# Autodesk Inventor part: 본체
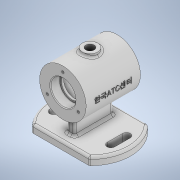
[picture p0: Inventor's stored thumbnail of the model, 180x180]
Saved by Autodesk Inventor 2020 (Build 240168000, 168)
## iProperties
Created: 2021-09
Part Number: 본체
Material: Generic
Document SubType Name: Modeling
Designer: Administrator
Density: 1 g/cm^3
Appearance: Default
Author: Administrator
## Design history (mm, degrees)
sketch "스케치1"
  geometry: C1 r 30 at (0, 0); 1 further point
  constraints: 1 centre point, 1 coincident
  dimensions: "d0" = 60 diameter of C1
extrude "돌출1" new body sketch "스케치1" stored distance "d1" = 70; taper "d2" = 0 deg
node "작업 평면1"
sketch "스케치2"
  geometry: C1 r 52.5 at (0, 0); 1 further point
  constraints: 1 centre point, 1 coincident
  dimensions: "d4" = 105 diameter of C1
extrude "돌출2" join sketch "스케치2" distance "d5" = 10; taper "d6" = 0 deg
sketch "스케치3"
  geometry: L1 (36.458, 37.5)-(-36.458, 37.5); L2 (-36.458, -37.5)-(36.458, -37.5); L3 (-36.458, -37.5)-(-36.742, -37.5); L4 (36.458, -37.5)-(36.742, -37.5); L5 (36.458, 37.5)-(36.742, 37.5); L6 (-36.458, 37.5)-(-36.742, 37.5); A1 r 52.5 centre (0, 0) between (-36.742, -37.5) and (36.742, -37.5) reference; A2 r 52.5 centre (0, 0) between (-36.742, -37.5) and (36.742, -37.5) reference; 3 further points
  constraints: 12 end point, 4 horizontal, 4 point on circle, 1 parallel, 1 point on line
  dimensions: "d7" = 75 distance of L1.end L2.start
extrude "돌출3" cut sketch "스케치3" distance "d8" = 10; taper "d9" = 0 deg
sketch "스케치4"
  geometry: L1 (-25.13, 25)-(-60.104, 25); L2 (-60.104, 25)-(-60.104, -25); L3 (-60.104, -25)-(-25.13, -25); L4 (-25.13, -25)-(-25.13, 25); 2 further points
  constraints: 8 end point, 2 parallel, 1 horizontal, 1 horizontal alignment, 1 midpoint, 1 perpendicular
  dimensions: "d10" = 50 distance of L1.end L2.end
extrude "돌출4" join sketch "스케치4" stored distance "d11" = 10; taper "d12" = 0 deg
sketch "스케치5"
  geometry: L1 (-37, -10)-(-37, 10); L2 (-32, -10)-(-32, 10); L3 (-42, 10)-(-42, -10); L4 (0, 0)-(0, 55.124); L5 (37, -10)-(37, 10); L6 (32, -10)-(32, 10); L7 (42, 10)-(42, -10); A1 r 5 centre (-37, -10) between (-42, -10) and (-32, -10); A2 r 5 centre (-37, 10) between (-32, 10) and (-42, 10); A3 r 5 centre (37, -10) between (32, -10) and (42, -10); A4 r 5 centre (37, 10) between (42, 10) and (32, 10); 2 further points
  constraints: 18 end point, 8 point on circle, 7 symmetric about line, 4 centre point, 4 tangent, 2 vertical, 1 horizontal alignment, 1 midpoint, 1 parallel, 2 other
  dimensions: "d13" = 20 distance of L1.start L1.end; "d14" = 10 diameter of A2; "d15" = 37 distance of point (-37, 0) L4.start
extrude "돌출5" cut sketch "스케치5" distance "d16" = 10; taper "d17" = 0 deg
sketch "스케치6"
  geometry: L1 (30, 35)-(-30, 35) reference; L2 (0, 35)-(16, 35); L3 (16, 35)-(16, 23.3); L4 (15.7, 23)-(0, 23); L5 (0, 23)-(0, 35); L6 (0, 23)-(14, 23); L7 (14, 23)-(14, 20); L8 (14, 20)-(0, 20); L9 (0, 20)-(0, 23); L10 (0, 20)-(25, 20); L11 (25, 20)-(25, -20); L12 (25, -20)-(0, -20); L13 (0, -20)-(0, 20); L14 (0, -20)-(14, -20); L15 (14, -20)-(14, -23); L16 (14, -23)-(0, -23); L17 (0, -23)-(0, -20); L18 (-30, -35)-(30, -35) reference; L19 (0, -23)-(15.7, -23); L20 (16, -23.3)-(16, -35); L21 (16, -35)-(0, -35); L22 (0, -35)-(0, -23); A1 r 0.3 centre (15.7, 23.3) between (15.7, 23) and (16, 23.3); A2 r 0.3 centre (15.7, -23.3) between (16, -23.3) and (15.7, -23); 11 further points
  constraints: 40 end point, 10 parallel, 5 horizontal, 5 perpendicular, 5 point on line, 4 point on circle, 4 tangent, 3 midpoint, 2 centre point, 1 equal radius, 1 horizontal alignment
  dimensions: "d18" = 50 diameter of L11 L13; "d19" = 40 distance of L10.end L11.end; "d20" = 32 diameter of L3 L5; "d21" = 28 diameter of L7 L9; "d22" = 32 diameter of L20 L22; "d23" = 28 diameter of L15 L17; "d24" = 12 distance of point (16, -23) L20.end; "d25" = 12 distance of L2.end point (16, 23); "d26" = 0.3 radius of A1
revolve "회전1" sketch "스케치6" stored, may be unused: angle "d27" = 90 deg
node "작업 평면2"
sketch "스케치7"
  geometry: C1 r 10 at (0, 0); 1 further point
  constraints: 1 centre point, 1 coincident
  dimensions: "d29" = 20 diameter of C1
extrude "돌출6" join sketch "스케치7" stored distance "d30" = 10; taper "d31" = 0 deg
sketch "스케치8"
  geometry: C1 r 10 at (0, 0) reference; 2 further points
  constraints: 1 coincident
hole "구멍1" sketch "스케치8" at (0, 0) diameter "d32" = 10.917; stored, may be unused: countersink angle "d36" = 90 deg, drill point angle "d38" = 118 deg; dims "d33" = 24, "d34" = 4, "d35" = 2, "d37" = 29.1
sketch "스케치9" dims "d39" = 46
  geometry: C1 r 16 at (0, 0) reference; 3 further points
  constraints: 2 vertical alignment, 1 coincident, 2 other
hole "구멍2" sketch "스케치9" at (0, 23) diameter "d40" = 3.242; stored, may be unused: countersink angle "d44" = 90 deg, drill point angle "d46" = 118 deg; dims "d41" = 8, "d42" = 4, "d43" = 2, "d45" = 10
node "작업 평면3"
sketch "스케치10"
  geometry: L1 (30, 35)-(-30, 35) reference; L2 (30, -35)-(30, 35) reference; 2 further points
  constraints: 1 other
  dimensions: "d50" = 35 distance from line of point (0, 0) L1; "d51" = 30 distance from line of point (0, 0) L2
feature "엠보싱1" sketch "스케치10" dims "d52" = 0.5, "d53" = 0
fillet "모깎기1" dims "d54" = 3
fillet "모깎기2" dims "d55" = 3
fillet "모깎기3" dims "d56" = 3
chamfer "모따기1" distance "d57" = 1; stored, may be unused: second distance "d58" = 2, angle "d59" = 45 deg
fillet "모깎기4" dims "d60" = 3
fillet "모깎기5" dims "d61" = 3
fillet "모깎기6" dims "d62" = 3
node "솔리드1"
pattern_circular "원형 패턴1" dims angle "d48" = 360 deg
mirror "미러1"
node "투영된 루프1"
feature "A9D066F2-1C7D-4E18-AEED-F7BC21143FA4" dims "d40" = 3.242, "d41" = 8, "d42" = 4, "d43" = 2, "d44" = 90 deg, "d45" = 10, "d46" = 118 deg
other parameters: "d3" = -62, "d28" = 33
